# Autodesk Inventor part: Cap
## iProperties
Shininess: 77.0
Length Units: 11269
Angle Units: 11279
Time Units: 11290
Mass Units: 11283
Length Display Precision: 3
Angle Display Precision: 2
Created: 2002-02
Part Number: Cap
Document SubType Name: Modeling
Designer: ***
Density: 1 g/cm^3
Density: 0.0
Volumn: 0.0
Area: 0.0
PropertySet Name: Model Information
Control State: 0
Master: False
Checked Out: False
Author: ***
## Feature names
1. Extrusion1
2. Extrusion2
3. Hole1
4. Hole2
5. Mirror1
6. Hole3
